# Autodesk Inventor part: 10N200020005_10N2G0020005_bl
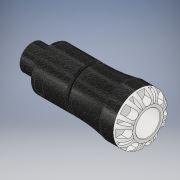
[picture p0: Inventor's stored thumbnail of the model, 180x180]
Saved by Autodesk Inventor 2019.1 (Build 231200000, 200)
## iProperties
Created: 2016-12
Part Number: 10N200020005_10N2G0020005_bl
Material: PVC-Piping
Description: PLASSON MALE ADAPTOR 20X1/2" SERIES 1
Document SubType Name: Modeling
Designer: KIM
Mass: 61.7504 g
Surface Area: 140.097 cm^2
Volume: 44.1074 cm^3
Density: 1.4 g/cm^3
Appearance: Black Cast
Author: KIM
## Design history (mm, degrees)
derived "10N20.ipt"
feature "Solid1::10N20.ipt" dims "ScaleForDerivedMember" = 10
tag "TaggingFeature1"
body "Solid1"
other parameters: "d0" = 95 [user parameter], "d1" = 18.9 [user parameter], "d3" = 25 [user parameter], "d4" = 41 [user parameter], "d6" = 45 [user parameter], "d8" = 34.85 [user parameter], "d13" = 6.4 [user parameter], "d14" = 6.4 [user parameter], "d15" = 0 [user parameter], "d17" = 360 deg [user parameter], "d19" = 8 deg [user parameter], "d20" = 0.4 [user parameter], "d21" = 0.4 [user parameter], "d22" = 8 deg [user parameter], "d24" = 0 [user parameter], "d26" = 360 deg [user parameter], "d32" = 0.925 [user parameter], "d33" = 4.1 [user parameter], "d34" = 20.955 [user parameter], "d35" = 2.5 [user parameter], "d38" = 16 [user parameter], "d39" = 0.62865 [user parameter], "d42" = 7 [user parameter], "d43" = 4.6 [user parameter], "d45" = 12.544 [user parameter], "d46" = 0 [user parameter], "d59" = 360 deg [user parameter], "d61" = 5.95 [user parameter], "d62" = 0.4 [user parameter], "d64" = 0 [user parameter], "d65" = 0.41 [user parameter], "d69" = 2 [user parameter], "d70" = 1.425 [user parameter], "d71" = 3 [user parameter], "d73" = 1 [user parameter], "E_" = 41 [user parameter], "H_" = 95 [user parameter], "l_" = 45 [user parameter], "R_" = 20.955 [user parameter], "l_2" = 16 [user parameter], "d9" = 8 [user parameter], "d11" = 41 [user parameter], "d12" = 25 [user parameter]
